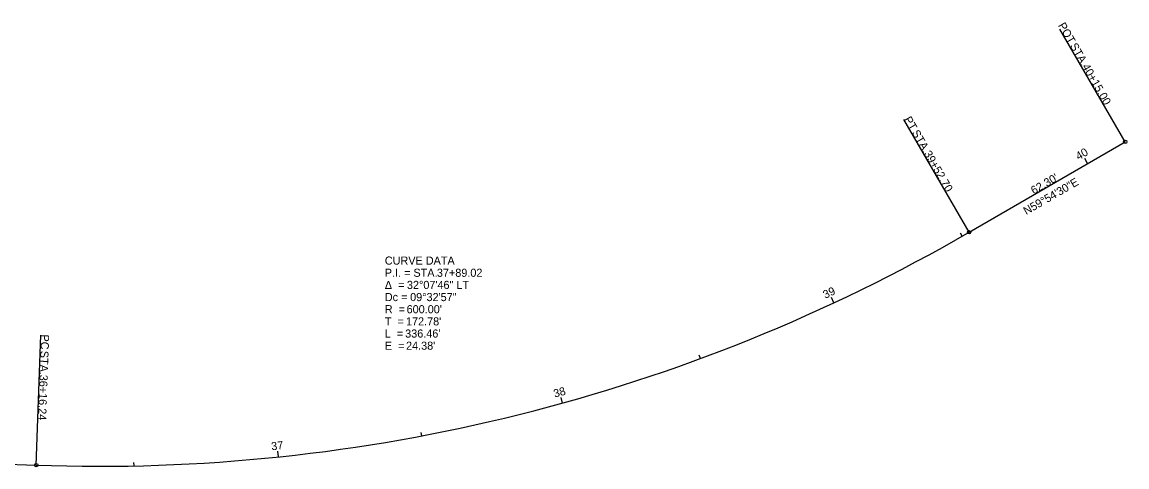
# Model space of a CAD drawing. Extents: x 1927094 to 1928117, y 199395 to 200287.
# Drawn here: x 1927735.6 to 1928117.2, y 199730.9 to 199884.6 of the extents above; entities that cross this region are included whole.
import ezdxf

# ---------------------------------------------------------------- set-up
doc = ezdxf.new("R2010")
doc.units = 0
for name, color, linetype in [('GE_X_Alignment', 7, 'Continuous'), ('GE_X_Alignment_100_Bearings', 7, 'Continuous'), ('GE_X_Alignment_100_Cardinal_Points', 7, 'Continuous'), ('GE_X_Alignment_100_Curve_Data', 7, 'Continuous'), ('GE_X_Alignment_100_Distances', 7, 'Continuous'), ('GE_X_Alignment_100_Stations', 7, 'Continuous')]:
    doc.layers.add(name, color=color, linetype=linetype)

msp = doc.modelspace()

# ---------------------------------------------------------------- linework, layer by layer
at = {"layer": 'GE_X_Alignment'}
for p, q in [((1928062.69, 199812.02), (1928116.6, 199843.26)), ((1927702.05, 199732.9), (1927740.52, 199731.53))]:
    msp.add_line(p, q, dxfattribs=at)
msp.add_arc((1927761.86, 200331.15), 600, 267.9622, 300.09168, dxfattribs=at)
at = {"layer": 'GE_X_Alignment_100_Cardinal_Points'}
for p, q in [((1928116.6, 199843.26), (1928094.03, 199882.19)), ((1928062.69, 199812.02), (1928040.13, 199850.95)), ((1927740.52, 199731.53), (1927742.12, 199776.5))]:
    msp.add_line(p, q, dxfattribs=at)
for centre in [(1928116.6, 199843.26), (1928062.69, 199812.02), (1927740.52, 199731.53)]:
    msp.add_circle(centre, 0.6, dxfattribs=at)
at = {"layer": 'GE_X_Alignment_100_Stations'}
for p, q in [((1928103.61, 199835.73), (1928102.61, 199837.46)), ((1928060.35, 199810.67), (1928059.75, 199811.71)), ((1928015.99, 199787.63), (1928015.14, 199789.44)), ((1927969.87, 199768.36), (1927969.45, 199769.49)), ((1927922.3, 199753), (1927921.77, 199754.93)), ((1927873.62, 199741.65), (1927873.4, 199742.83)), ((1927824.16, 199734.4), (1927823.96, 199736.38)), ((1927774.28, 199731.28), (1927774.25, 199732.48))]:
    msp.add_line(p, q, dxfattribs=at)

# ---------------------------------------------------------------- texts
at = {"layer": 'GE_X_Alignment_100_Bearings'}
msp.add_text('N59°54\'30"E', height=2.8, rotation=30.0917, dxfattribs=at).set_placement((1928082.43, 199817.91))
at = {"layer": 'GE_X_Alignment_100_Cardinal_Points'}
for s, rotation, p in [('POT', 300.0917, (1928093.32, 199883.49)), (' STA. ', 300.0917, (1928096.9, 199877.32)), ('40+15.00', 300.0917, (1928101.57, 199869.26)), ('PT', 300.0917, (1928040.11, 199851.05)), (' STA. ', 300.0917, (1928042.29, 199847.29)), ('39+52.70', 300.0917, (1928046.97, 199839.22)), ('PC', 267.9622, (1927742.17, 199776.73)), (' STA. ', 267.9622, (1927742, 199772.13)), ('36+16.24', 267.9622, (1927741.67, 199762.82))]:
    msp.add_text(s, height=2.8, rotation=rotation, dxfattribs=at).set_placement(p)
at = {"layer": 'GE_X_Alignment_100_Curve_Data'}
for s, p in [('CURVE DATA', (1927860.89, 199800.82)), ('P.I. = STA. ', (1927860.89, 199796.62)), ('37+89.02', (1927878.88, 199796.62)), ('Δ  = ', (1927860.89, 199792.42)), ('32°07\'46" LT', (1927868.53, 199792.42)), ('Dc = ', (1927860.89, 199788.22)), ('09°32\'57"', (1927869.63, 199788.22)), ('R  = ', (1927860.89, 199784.02)), ("600.00'", (1927868.42, 199784.02)), ('T  = ', (1927860.89, 199779.82)), ("172.78'", (1927868.21, 199779.82)), ('L  = ', (1927860.89, 199775.62)), ("336.46'", (1927867.92, 199775.62)), ('E  = ', (1927860.89, 199771.42)), ("24.38'", (1927868.23, 199771.42))]:
    msp.add_text(s, height=2.8, dxfattribs=at).set_placement(p)
at = {"layer": 'GE_X_Alignment_100_Distances'}
msp.add_text("62.30'", height=2.8, rotation=30.0917, dxfattribs=at).set_placement((1928085.02, 199825))
at = {"layer": 'GE_X_Alignment_100_Stations'}
for s, rotation, p in [('40', 30.0917, (1928100.5, 199836.82)), ('39', 25.0592, (1928013.02, 199789)), ('38', 15.5099, (1927919.58, 199754.84)), ('37', 5.9606, (1927821.79, 199736.66))]:
    msp.add_text(s, height=2.8, rotation=rotation, dxfattribs=at).set_placement(p)

doc.saveas('drawing.dxf')
